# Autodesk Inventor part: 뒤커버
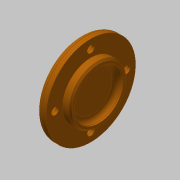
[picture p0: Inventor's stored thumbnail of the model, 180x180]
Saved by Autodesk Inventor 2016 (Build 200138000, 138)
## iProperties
Created: 2019-06
Part Number: 뒤커버
Material: 알루미늄 6061
Document SubType Name: Modeling
Designer: mduedu
Density: 1 g/cm^3
Appearance: 주황색
Author: mduedu
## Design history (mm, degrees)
sketch "스케치1"
  geometry: L1 (0, 0)-(-5, 0); L2 (-5, 0)-(-5, 17.5); L3 (-5, 17.5)-(0, 17.5); L4 (0, 17.5)-(0, 0); L5 (-5, 0)-(-11, 0); L6 (-11, 0)-(-11, 27.5); L7 (-11, 27.5)-(-5, 27.5); L8 (-5, 27.5)-(-5, 0)
  constraints: 16 end point, 4 parallel, 2 horizontal, 2 perpendicular
  dimensions: "d0" = 11 distance between parallel lines of L4 L6; "d2" = 5 distance of L2.end L3.end; "d3" = 55 diameter of L7 L5; "d4" = 35 diameter of L3 L1
revolve "회전1" sketch "스케치1" stored, may be unused: angle "d5" = 90 deg
sketch "스케치2"
  geometry: C1 r 15 at (0, 0); 1 further point
  constraints: 1 centre point, 1 coincident
  dimensions: "d6" = 30 diameter of C1
extrude "돌출1" cut sketch "스케치2" distance "d7" = 4; taper "d8" = 0 deg
fillet "모깎기1" dims "d9" = 3
fillet "모깎기2" dims "d10" = 3
chamfer "모따기1" distance "d11" = 1; stored, may be unused: second distance "d12" = 2, angle "d13" = 45 deg
sketch "스케치3" dims "d14" = 44
  geometry: 3 further points
  constraints: 2 vertical alignment, 1 coincident, 2 other
hole "구멍1" sketch "스케치3" at (0, 22) diameter "d15" = 4.5; stored, may be unused: countersink angle "d19" = 90 deg, drill point angle "d21" = 118 deg; dims "d16" = 6, "d17" = 8, "d18" = 4.4, "d20" = 8
node "솔리드1"
pattern_circular "원형 패턴1" dims angle "d23" = 360 deg
